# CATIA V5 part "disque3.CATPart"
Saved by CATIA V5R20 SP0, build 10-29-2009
Part number: disque1.1
Bounding box of the stored display mesh (mm): x 37.5 to 122.5, y 0 to 15, z 57.51 to 142.49
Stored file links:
  G:\TM_Rendule_19122012\Edeli_2012_190_gcausse\disque3.CATPart
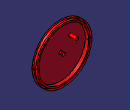
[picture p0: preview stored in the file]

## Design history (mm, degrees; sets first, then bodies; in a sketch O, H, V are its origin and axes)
Body1 (main body)
  DatumSurface1
  Sketch1 on face of DatumSurface1, origin (0, 5, 0), H (1, 0, 0), V (0, 0, 1)
    circle A1 centre (80, 100) radius 37.5
    circle A2 centre (80, 100) radius 2.5
    radius A1 = 37.5
    radius A2 = 2.5
  Pad1: profile Sketch1, direction (0, -1, 0), length 5
Body2
  Sketch2 on start face of Pad1, origin (0, 5, 0), H (-1, 0, 0), V (0, 0, 1)
    circle A1 centre (-80, 100) radius 40
    circle A2 centre (-80, 100) radius 37.5
    radius A2 = 37.5
    radius A1 = 40
  Pad2: profile Sketch2, direction (0, -1, 0), length 5
  Sketch3 on start face of Pad1, origin (0, 5, 0), H (-1, 0, 0), V (0, 0, 1)
Body3
  Sketch4 on start face of Pad1, origin (0, 5, 0), H (-1, 0, 0), V (0, 0, 1)
    circle A1 centre (-80, 100) radius 40
    circle A2 centre (-80, 100) radius 42.5
    radius A2 = 42.5
    radius A1 = 40
  Pad3: profile Sketch4, direction (0, -1, 0), length 5
  Sketch5 on start face of Pad1, origin (0, 5, 0), H (-1, 0, 0), V (0, 0, 1)
    circle A1 centre (-70, 120) radius 2.5
    radius A1 = 2.5
  Pad4: profile Sketch5, direction (0, 1, 0), length 10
